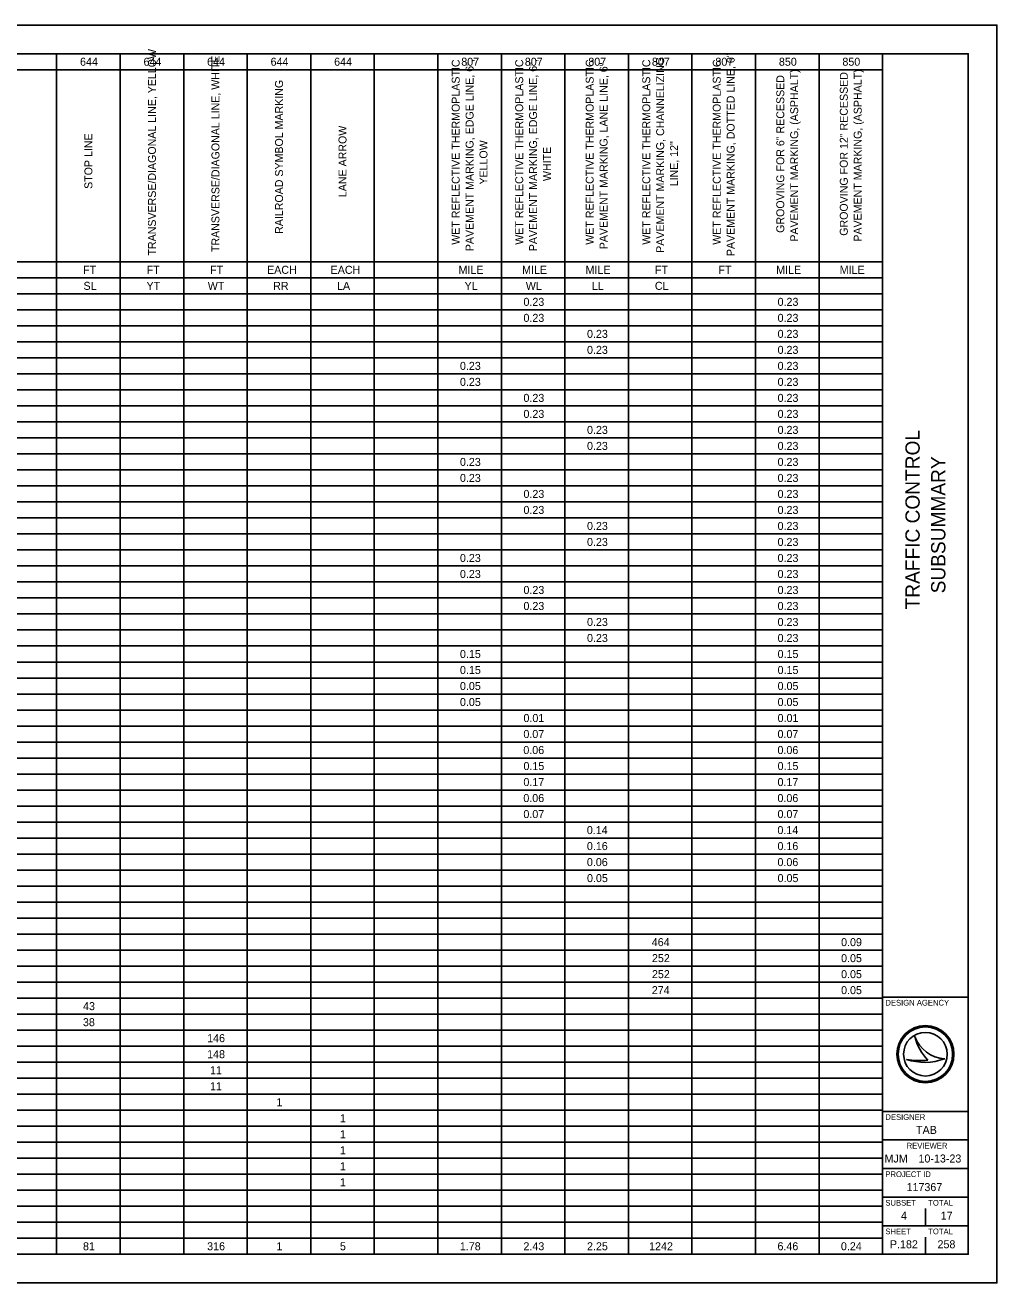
# Model space of a CAD drawing. Extents: x 0 to 34, y 0 to 22.
# Drawn here: x 17 to 34, y 0 to 22 of the extents above; entities that cross this region are included whole.
import ezdxf

# ---------------------------------------------------------------- set-up
doc = ezdxf.new("R2010")
doc.units = 0
for name, color, linetype in [('Default', 7, 'Continuous'), ('SH_Border', 7, 'Continuous'), ('SH_Cut_Line', 7, 'Continuous'), ('SH_Data', 7, 'Continuous')]:
    doc.layers.add(name, color=color, linetype=linetype)

msp = doc.modelspace()

# ---------------------------------------------------------------- linework, layer by layer
at = {"layer": 'Default'}
for p, q in [((1.5, 21.5), (32, 21.5)), ((17.551, 21.5), (17.551, 0.5)), ((18.662, 21.5), (18.662, 0.5)), ((19.774, 21.5), (19.774, 0.5)), ((20.885, 21.5), (20.885, 0.5)), ((21.997, 21.5), (21.997, 0.5)), ((23.108, 21.5), (23.108, 0.5)), ((24.22, 21.5), (24.22, 0.5)), ((25.331, 21.5), (25.331, 0.5)), ((26.443, 21.5), (26.443, 0.5)), ((27.554, 21.5), (27.554, 0.5)), ((28.666, 21.5), (28.666, 0.5)), ((29.777, 21.5), (29.777, 0.5)), ((30.889, 21.5), (30.889, 0.5)), ((32, 21.5), (32, 0.5)), ((8.659, 21.22), (32, 21.22)), ((8.659, 17.86), (32, 17.86)), ((1.5, 17.58), (32, 17.58)), ((1.5, 17.3), (32, 17.3)), ((1.5, 17.02), (32, 17.02)), ((1.5, 16.74), (32, 16.74)), ((1.5, 16.46), (32, 16.46)), ((1.5, 16.18), (32, 16.18)), ((1.5, 15.9), (32, 15.9)), ((1.5, 15.62), (32, 15.62)), ((1.5, 15.34), (32, 15.34)), ((1.5, 15.06), (32, 15.06)), ((1.5, 14.78), (32, 14.78)), ((1.5, 14.5), (32, 14.5)), ((1.5, 14.22), (32, 14.22)), ((1.5, 13.94), (32, 13.94)), ((1.5, 13.66), (32, 13.66)), ((1.5, 13.38), (32, 13.38)), ((1.5, 13.1), (32, 13.1)), ((1.5, 12.82), (32, 12.82)), ((1.5, 12.54), (32, 12.54)), ((1.5, 12.26), (32, 12.26)), ((1.5, 11.98), (32, 11.98)), ((1.5, 11.7), (32, 11.7)), ((1.5, 11.42), (32, 11.42)), ((1.5, 11.14), (32, 11.14)), ((1.5, 10.86), (32, 10.86)), ((1.5, 10.58), (32, 10.58)), ((1.5, 10.3), (32, 10.3)), ((1.5, 10.02), (32, 10.02)), ((1.5, 9.74), (32, 9.74)), ((1.5, 9.46), (32, 9.46)), ((1.5, 9.18), (32, 9.18)), ((1.5, 8.9), (32, 8.9)), ((1.5, 8.62), (32, 8.62)), ((1.5, 8.34), (32, 8.34)), ((1.5, 8.06), (32, 8.06)), ((1.5, 7.78), (32, 7.78)), ((1.5, 7.5), (32, 7.5)), ((1.5, 7.22), (32, 7.22)), ((1.5, 6.94), (32, 6.94)), ((1.5, 6.66), (32, 6.66)), ((1.5, 6.38), (32, 6.38)), ((1.5, 6.1), (32, 6.1)), ((1.5, 5.82), (32, 5.82)), ((1.5, 5.54), (32, 5.54)), ((1.5, 5.26), (32, 5.26)), ((1.5, 4.98), (32, 4.98)), ((1.5, 4.7), (32, 4.7)), ((1.5, 4.42), (32, 4.42)), ((1.5, 4.14), (32, 4.14)), ((1.5, 3.86), (32, 3.86)), ((1.5, 3.58), (32, 3.58)), ((1.5, 3.3), (32, 3.3)), ((1.5, 3.02), (32, 3.02)), ((1.5, 2.74), (32, 2.74)), ((1.5, 2.46), (32, 2.46)), ((1.5, 2.18), (32, 2.18)), ((1.5, 1.9), (32, 1.9)), ((1.5, 1.62), (32, 1.62)), ((1.5, 1.34), (32, 1.34)), ((1.5, 1.06), (32, 1.06)), ((1.5, 0.78), (32, 0.78)), ((1.5, 0.5), (32, 0.5))]:
    msp.add_line(p, q, dxfattribs=at)
at = {"layer": 'SH_Border'}
for p, q in [((32, 0.5), (32, 21.5)), ((32, 5), (33.5, 5)), ((32, 3), (33.5, 3)), ((32, 2.5), (33.5, 2.5)), ((32, 2), (33.5, 2)), ((32, 1.5), (33.5, 1.5)), ((32, 1), (33.5, 1))]:
    msp.add_line(p, q, dxfattribs=at)
msp.add_lwpolyline([(1.5, 21.5), (33.5, 21.5), (33.5, 0.5), (1.5, 0.5)], close=True, dxfattribs=at)
at = {"layer": 'SH_Cut_Line'}
msp.add_lwpolyline([(0, 0), (34, 0), (34, 22), (0, 22)], close=True, dxfattribs=at)
at = {"layer": 'SH_Data'}
for p, q in [((32.567, 4.31), (32.567, 4.31)), ((32.75, 4), (32.75, 4)), ((32.417, 3.91), (32.417, 3.91)), ((33.087, 3.919), (33.087, 3.919)), ((32.75, 1), (32.75, 1.3)), ((32.375, 0.675), (32.375, 0.675)), ((32.75, 0.5), (32.75, 0.8))]:
    msp.add_line(p, q, dxfattribs=at)
for radius in [0.5, 0.477, 0.477, 0.382]:
    msp.add_circle((32.75, 4), radius, dxfattribs=at)
for centre, radius, start, end in [((33.116, 4.498), 0.58, 198.9257, 198.9319), ((33.347, 4.47), 0.796, 191.6379, 191.6421), ((33.116, 4.498), 0.58, 198.9319, 267.1657), ((33.347, 4.47), 0.796, 191.6421, 226.0947), ((32.739, 4.87), 1.013, 251.4576, 290.0832), ((32.648, 5.154), 1.266, 259.4964, 259.4995), ((32.739, 4.87), 1.013, 251.4527, 251.4576), ((32.648, 5.154), 1.266, 259.4995, 276.6672)]:
    msp.add_arc(centre, radius, start, end, dxfattribs=at)

# ---------------------------------------------------------------- texts
at = {"layer": 'Default'}
for s, height, p in [('TRANSVERSE/DIAGONAL LINE, YELLOW', 0.13893, (19.288, 17.97)), ('TRANSVERSE/DIAGONAL LINE, WHITE', 0.13893, (20.399, 18.031)), ('WET REFLECTIVE THERMOPLASTIC ', 0.13893, (24.602, 18.159)), ('PAVEMENT MARKING, EDGE LINE, 6", ', 0.13893, (24.845, 18.046)), ('WET REFLECTIVE THERMOPLASTIC ', 0.13893, (25.713, 18.159)), ('PAVEMENT MARKING, EDGE LINE, 6", ', 0.13893, (25.956, 18.046)), ('WET REFLECTIVE THERMOPLASTIC ', 0.13893, (26.946, 18.159)), ('WET REFLECTIVE THERMOPLASTIC ', 0.13893, (27.936, 18.159)), ('PAVEMENT MARKING, CHANNELIZING ', 0.13893, (28.179, 18.017)), ('WET REFLECTIVE THERMOPLASTIC ', 0.13893, (29.169, 18.159)), ('PAVEMENT MARKING, DOTTED LINE, 6"', 0.13893, (29.412, 17.96)), ('PAVEMENT MARKING, LANE LINE, 6"', 0.13893, (27.189, 18.08)), ('PAVEMENT MARKING, (ASPHALT)', 0.13893, (30.524, 18.213)), ('GROOVING FOR 12" RECESSED ', 0.13893, (31.392, 18.316)), ('PAVEMENT MARKING, (ASPHALT)', 0.13893, (31.635, 18.213)), ('RAILROAD SYMBOL MARKING', 0.13893, (21.511, 18.349)), ('GROOVING FOR 6" RECESSED ', 0.13893, (30.281, 18.367)), ('LANE ARROW', 0.1389, (22.622, 18.992)), ('STOP LINE', 0.1389, (18.176, 19.136)), ('YELLOW', 0.1389, (25.088, 19.212)), ('WHITE', 0.1389, (26.2, 19.273)), ('LINE, 12"', 0.1389, (28.422, 19.181))]:
    msp.add_text(s, height=height, rotation=90, dxfattribs=at).set_placement(p)
for s, p in [('644', (17.96, 21.29)), ('644', (19.071, 21.29)), ('644', (20.183, 21.29)), ('644', (21.294, 21.29)), ('644', (22.406, 21.29)), ('807', (24.63, 21.29)), ('807', (25.742, 21.29)), ('807', (26.853, 21.29)), ('807', (27.965, 21.29)), ('807', (29.076, 21.29)), ('850', (30.187, 21.29)), ('850', (31.298, 21.29)), ('FT', (18.014, 17.65)), ('FT', (19.126, 17.65)), ('FT', (20.237, 17.65)), ('EACH', (21.232, 17.65)), ('EACH', (22.344, 17.65)), ('MILE', (24.582, 17.65)), ('MILE', (25.694, 17.65)), ('MILE', (26.805, 17.65)), ('FT', (28.017, 17.65)), ('FT', (29.129, 17.65)), ('MILE', (30.139, 17.65)), ('MILE', (31.251, 17.65)), ('SL', (18.021, 17.37)), ('YT', (19.123, 17.37)), ('WT', (20.195, 17.37)), ('RR', (21.338, 17.37)), ('LA', (22.456, 17.37)), ('YL', (24.687, 17.37)), ('WL', (25.759, 17.37)), ('LL', (26.916, 17.37)), ('CL', (28.017, 17.37)), ('0.23', (25.718, 17.09)), ('0.23', (30.164, 17.09)), ('0.23', (25.718, 16.81)), ('0.23', (30.164, 16.81)), ('0.23', (26.83, 16.53)), ('0.23', (30.164, 16.53)), ('0.23', (26.83, 16.25)), ('0.23', (30.164, 16.25)), ('0.23', (24.607, 15.97)), ('0.23', (30.164, 15.97)), ('0.23', (24.607, 15.69)), ('0.23', (30.164, 15.69)), ('0.23', (25.718, 15.41)), ('0.23', (30.164, 15.41)), ('0.23', (25.718, 15.13)), ('0.23', (30.164, 15.13)), ('0.23', (26.83, 14.85)), ('0.23', (30.164, 14.85)), ('0.23', (26.83, 14.57)), ('0.23', (30.164, 14.57)), ('0.23', (24.607, 14.29)), ('0.23', (30.164, 14.29)), ('0.23', (24.607, 14.01)), ('0.23', (30.164, 14.01)), ('0.23', (25.718, 13.73)), ('0.23', (30.164, 13.73)), ('0.23', (25.718, 13.45)), ('0.23', (30.164, 13.45)), ('0.23', (26.83, 13.17)), ('0.23', (30.164, 13.17)), ('0.23', (26.83, 12.89)), ('0.23', (30.164, 12.89)), ('0.23', (24.607, 12.61)), ('0.23', (30.164, 12.61)), ('0.23', (24.607, 12.33)), ('0.23', (30.164, 12.33)), ('0.23', (25.718, 12.05)), ('0.23', (30.164, 12.05)), ('0.23', (25.718, 11.77)), ('0.23', (30.164, 11.77)), ('0.23', (26.83, 11.49)), ('0.23', (30.164, 11.49)), ('0.23', (26.83, 11.21)), ('0.23', (30.164, 11.21)), ('0.15', (24.607, 10.93)), ('0.15', (30.164, 10.93)), ('0.15', (24.607, 10.65)), ('0.15', (30.164, 10.65)), ('0.05', (24.607, 10.37)), ('0.05', (30.164, 10.37)), ('0.05', (24.607, 10.09)), ('0.05', (30.164, 10.09)), ('0.01', (25.718, 9.81)), ('0.01', (30.164, 9.81)), ('0.07', (25.717, 9.53)), ('0.07', (30.163, 9.53)), ('0.06', (25.716, 9.25)), ('0.06', (30.162, 9.25)), ('0.15', (25.718, 8.97)), ('0.15', (30.164, 8.97)), ('0.17', (25.717, 8.69)), ('0.17', (30.163, 8.69)), ('0.06', (25.716, 8.41)), ('0.06', (30.162, 8.41)), ('0.07', (25.717, 8.13)), ('0.07', (30.163, 8.13)), ('0.14', (26.827, 7.85)), ('0.14', (30.161, 7.85)), ('0.16', (26.828, 7.57)), ('0.16', (30.162, 7.57)), ('0.06', (26.828, 7.29)), ('0.06', (30.162, 7.29)), ('0.05', (26.83, 7.01)), ('0.05', (30.164, 7.01)), ('464', (27.963, 5.89)), ('0.09', (31.275, 5.89)), ('252', (27.966, 5.61)), ('0.05', (31.275, 5.61)), ('252', (27.966, 5.33)), ('0.05', (31.275, 5.33)), ('274', (27.963, 5.05)), ('0.05', (31.275, 5.05)), ('43', (18.013, 4.77)), ('38', (18.011, 4.49)), ('146', (20.184, 4.21)), ('148', (20.184, 3.93)), ('11', (20.235, 3.65)), ('11', (20.235, 3.37)), ('1', (21.396, 3.09)), ('1', (22.508, 2.81)), ('1', (22.508, 2.53)), ('1', (22.508, 2.25)), ('1', (22.508, 1.97)), ('1', (22.508, 1.69)), ('81', (18.012, 0.57)), ('316', (20.184, 0.57)), ('1', (21.396, 0.57)), ('5', (22.508, 0.57)), ('1.78', (24.605, 0.57)), ('2.43', (25.718, 0.57)), ('2.25', (26.83, 0.57)), ('1242', (27.916, 0.57)), ('6.46', (30.162, 0.57)), ('0.24', (31.272, 0.57))]:
    msp.add_text(s, height=0.14, dxfattribs=at).set_placement(p)
at = {"layer": 'SH_Data'}
for s, p in [('TRAFFIC CONTROL', (32.65, 11.78)), ('SUBSUMMARY', (33.1, 12.061))]:
    msp.add_text(s, height=0.25, rotation=90, dxfattribs=at).set_placement(p)
for s, height, p in [('DESIGN AGENCY', 0.1, (32.05, 4.85)), ('DESIGNER', 0.1, (32.05, 2.85)), ('TAB', 0.14, (32.586, 2.605)), ('REVIEWER', 0.1, (32.422, 2.35)), ('MJM', 0.14, (32.035, 2.105)), ('10-13-23', 0.14, (32.629, 2.105)), ('PROJECT ID', 0.1, (32.05, 1.85)), ('117367', 0.14, (32.42, 1.605)), ('SUBSET', 0.1, (32.05, 1.35)), ('TOTAL', 0.1, (32.8, 1.35)), ('4', 0.14, (32.322, 1.105)), ('17', 0.14, (33.018, 1.105)), ('SHEET', 0.1, (32.05, 0.85)), ('TOTAL', 0.1, (32.8, 0.85)), ('P.182', 0.14, (32.129, 0.605)), ('258', 0.14, (32.962, 0.605))]:
    msp.add_text(s, height=height, dxfattribs=at).set_placement(p)

doc.saveas('drawing.dxf')
